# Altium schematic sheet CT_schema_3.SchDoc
size 313 x 200 mm
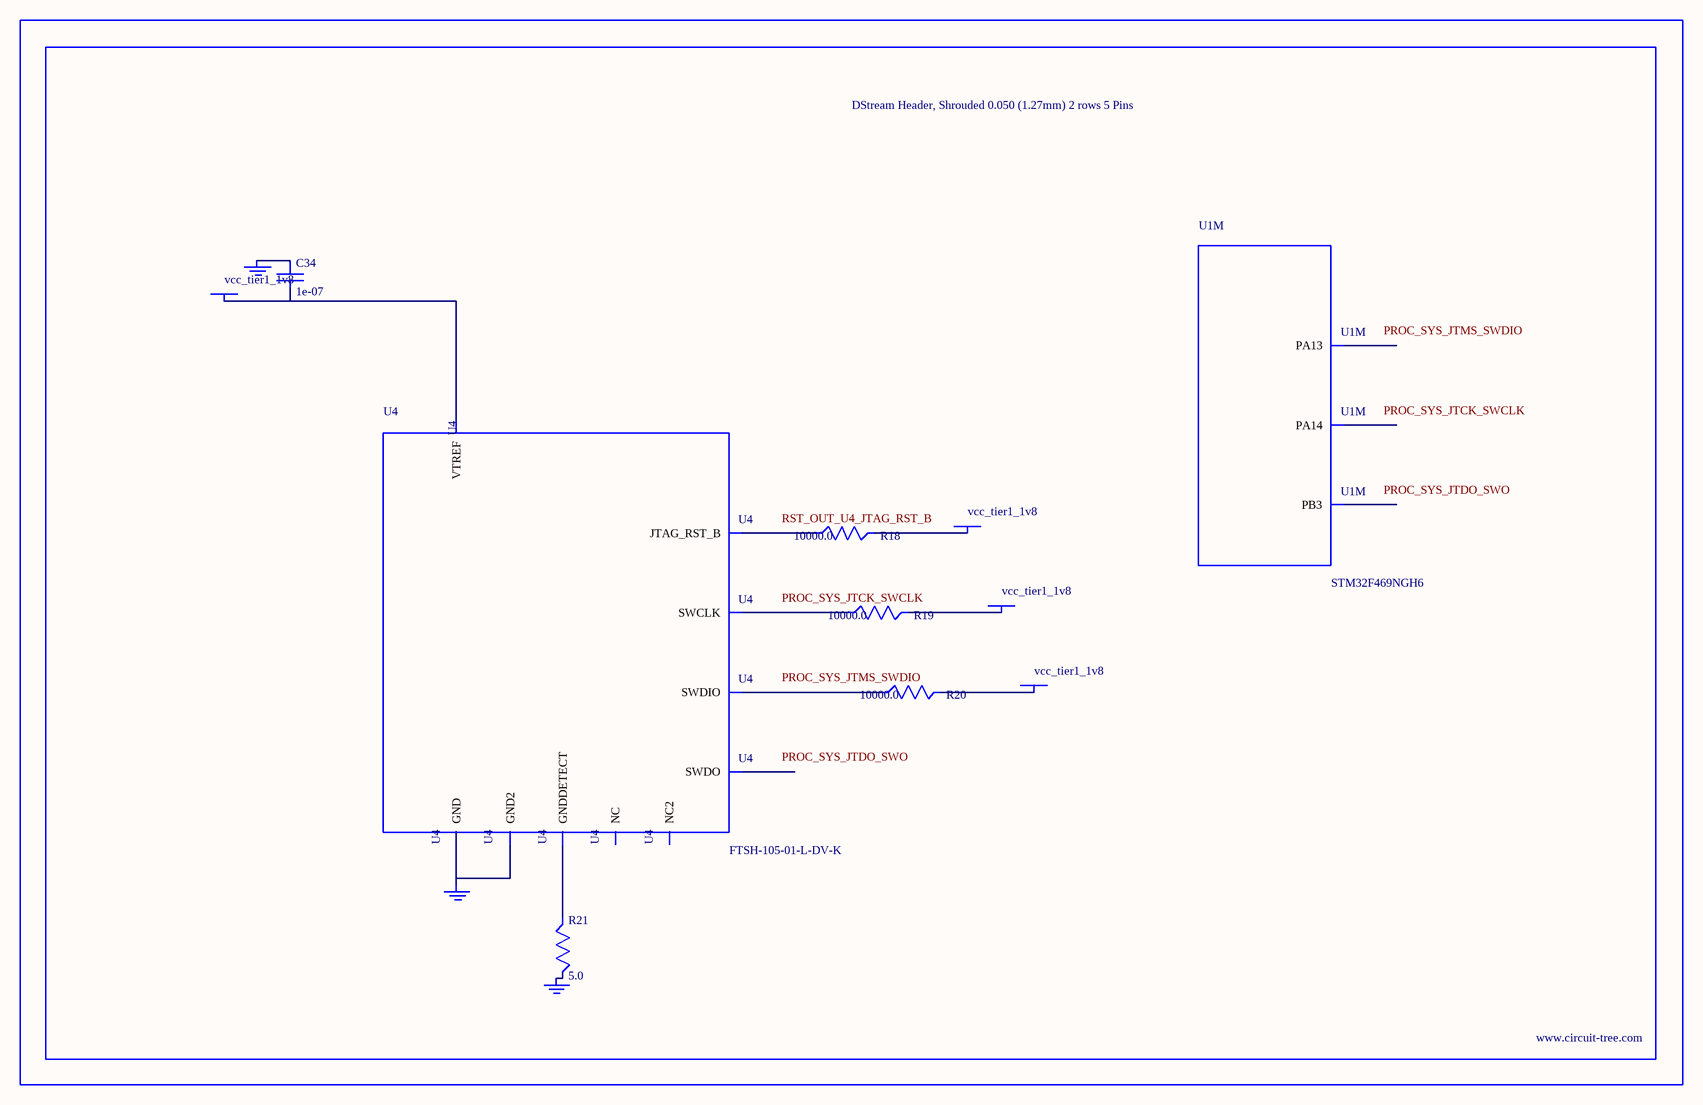
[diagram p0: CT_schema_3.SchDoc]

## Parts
BORDER2  (no value)
C34  1e-07  [C0402]
GND_INSTANCE_2_0  (no value)
GND_INSTANCE_2_1  (no value)
GND_INSTANCE_2_2  (no value)
POWER_INSTANCE_2_0  vcc_tier1_1v8
POWER_INSTANCE_2_1  vcc_tier1_1v8
POWER_INSTANCE_2_2  vcc_tier1_1v8
POWER_INSTANCE_2_3  vcc_tier1_1v8
R18  10000.0  [R0603]
R19  10000.0  [R0603]
R20  10000.0  [R0603]
R21  5.0  [R0603]
U1  STM32F469NGH6  [TFBGA216]  (part M of 16)
U4  FTSH-105-01-L-DV-K  [SAMTEC_FTSH-105-01-L-DV-K]

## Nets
NetC34_1: C34.1 GND_INSTANCE_2_0.0(GND)
NetC34_2: C34.2 POWER_INSTANCE_2_0.0(PWR) U4.1(VTREF)
NetGND_INSTANCE_2_1_0: GND_INSTANCE_2_1.0(GND) R21.2
NetGND_INSTANCE_2_2_0: GND_INSTANCE_2_2.0(GND) U4.3(GND) U4.5(GND2)
NetPOWER_INSTANCE_2_1_0: POWER_INSTANCE_2_1.0(PWR) R20.2
NetPOWER_INSTANCE_2_2_0: POWER_INSTANCE_2_2.0(PWR) R19.2
NetPOWER_INSTANCE_2_3_0: POWER_INSTANCE_2_3.0(PWR) R18.2
NetR18_1: R18.1 U4.10(JTAG_RST_B)
NetR19_1: R19.1 U4.4(SWCLK)
NetR20_1: R20.1 U4.2(SWDIO)
NetR21_1: R21.1 U4.9(GNDDETECT)

Not connected (* = marked no-connect by the designer): U1 A10(PB3) A14(PA14) A15(PA13); U4 6(SWDO) 7(NC) 8(NC2)

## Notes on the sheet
- Labels drawn without touching a wire or pin: PROC_SYS_JTCK_SWCLK, PROC_SYS_JTDO_SWO, PROC_SYS_JTMS_SWDIO, RST_OUT_U4_JTAG_RST_B

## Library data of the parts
BORDER2 = BORDER_PAGE2
C34 = C0402C104K3RACTU
GND_INSTANCE_2_0-GND_INSTANCE_2_2 = GND
POWER_INSTANCE_2_0-POWER_INSTANCE_2_3 = PWR
R18-R20 = RC0603JR-0710KL
R21 = ERJ-3GEYJ5R1V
